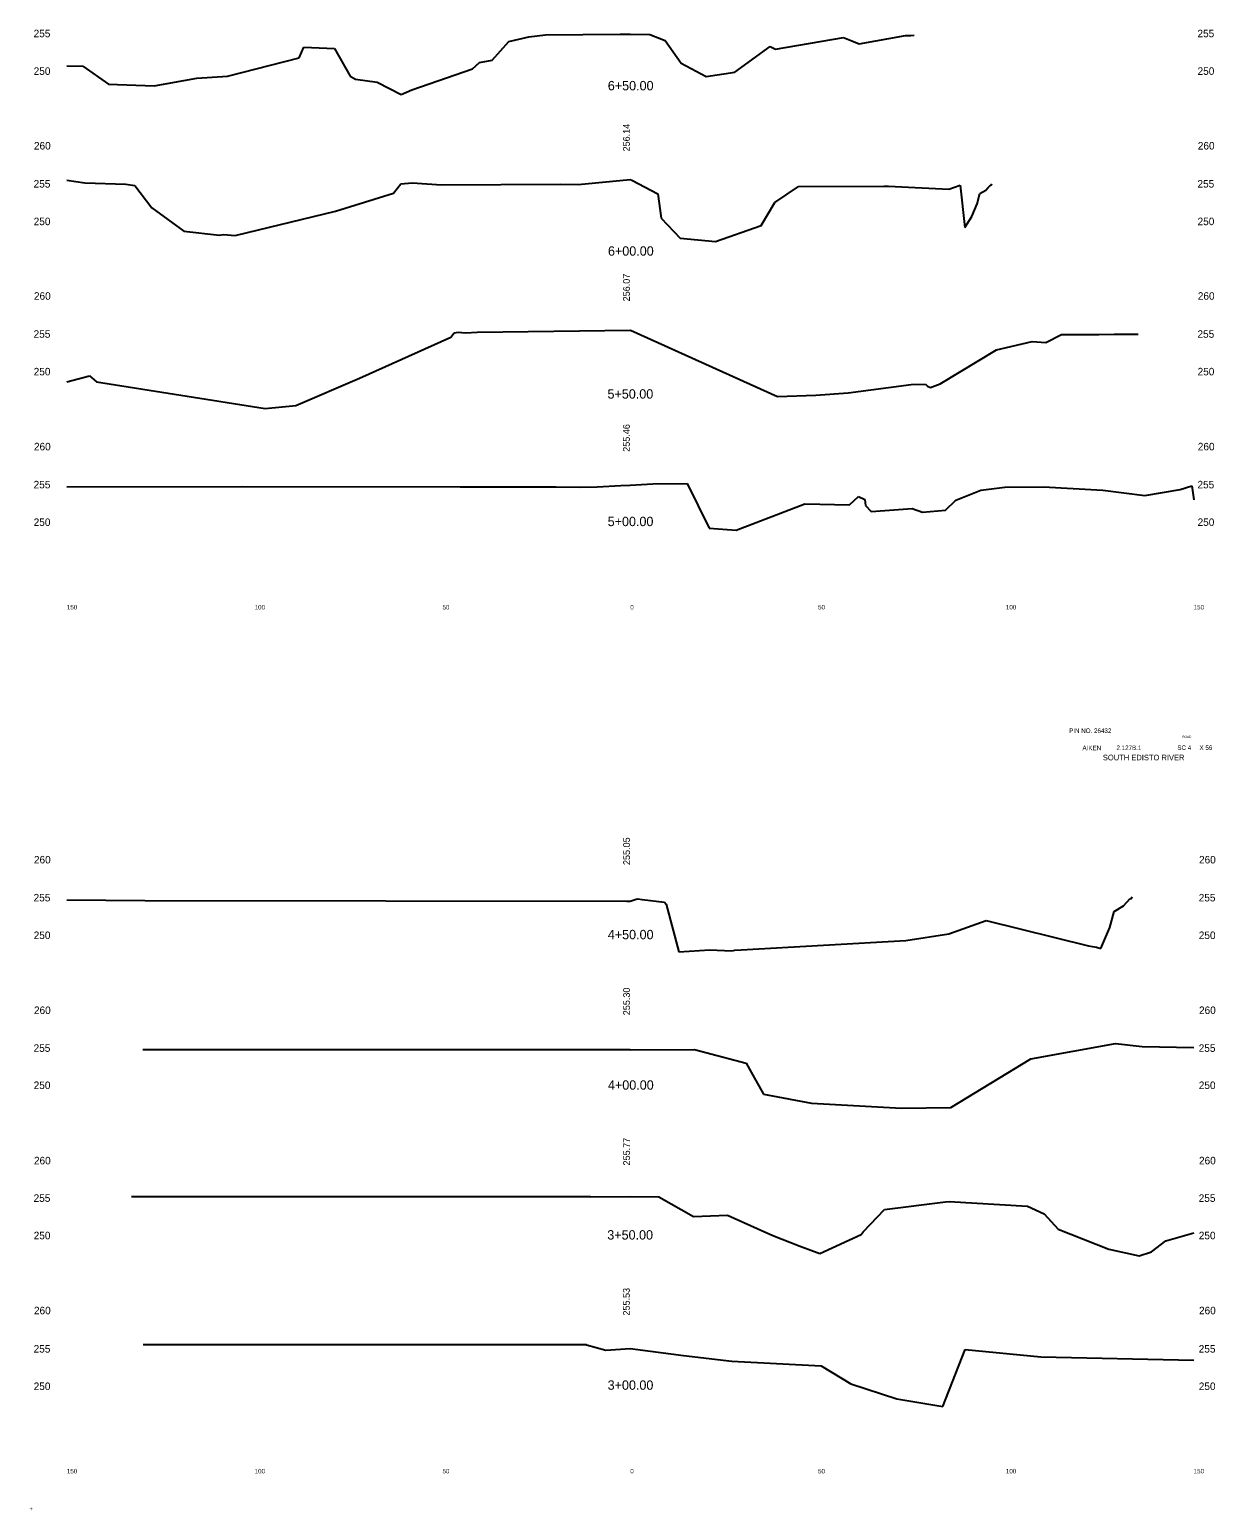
# Model space of a CAD drawing. Extents: x 557 to 872, y 628 to 2216.
# Drawn here: x 556.6 to 872.3, y 628 to 1022.2 of the extents above; entities that cross this region are included whole.
import ezdxf

# ---------------------------------------------------------------- set-up
doc = ezdxf.new("R2010")
doc.units = 0
for name, color, linetype in [('Level 1', 7, 'Continuous'), ('Level 10', 7, 'Continuous'), ('Level 13', 7, 'Continuous'), ('Level 3', 7, 'Continuous'), ('Level 60', 7, 'Continuous')]:
    doc.layers.add(name, color=color, linetype=linetype)

msp = doc.modelspace()

# ---------------------------------------------------------------- linework, layer by layer
at = {"layer": 'Level 60'}
for p, q in [((628.42, 1014.65), (629.6, 1017.48)), ((629.6, 1017.48), (637.79, 1017.18)), ((637.79, 1017.18), (641.99, 1009.73)), ((679.77, 1014.03), (684.22, 1018.98)), ((684.22, 1018.98), (689.54, 1020.23)), ((689.54, 1020.23), (693.95, 1020.75)), ((693.95, 1020.75), (713.85, 1020.96)), ((713.85, 1020.96), (716.54, 1020.93)), ((716.54, 1020.93), (721.78, 1020.86)), ((721.78, 1020.86), (725.81, 1019.29)), ((725.81, 1019.29), (730.12, 1013.19)), ((744.34, 1010.87), (753.83, 1017.71)), ((753.83, 1017.71), (755.24, 1017)), ((755.24, 1017), (773.34, 1020.09)), ((773.34, 1020.09), (775.5, 1019.22)), ((775.5, 1019.22), (777.5, 1018.41)), ((777.5, 1018.41), (789.84, 1020.58)), ((789.84, 1020.58), (791.27, 1020.64)), ((791.27, 1020.64), (792.16, 1020.65)), ((609.31, 1009.8), (628.42, 1014.65)), ((674.52, 1011.7), (676.36, 1013.43)), ((676.36, 1013.43), (679.77, 1014.03)), ((730.12, 1013.19), (736.79, 1009.69)), ((566.54, 1012.48), (570.83, 1012.4)), ((570.83, 1012.4), (577.58, 1007.64)), ((589.75, 1007.24), (601.14, 1009.26)), ((601.14, 1009.26), (609.31, 1009.8)), ((641.99, 1009.73), (643.38, 1009.01)), ((658.39, 1006.17), (674.52, 1011.7)), ((736.79, 1009.69), (744.34, 1010.87)), ((577.58, 1007.64), (589.75, 1007.24)), ((643.38, 1009.01), (649.14, 1008.15)), ((649.14, 1008.15), (655.55, 1004.86)), ((655.55, 1004.86), (658.39, 1006.17)), ((566.54, 982.08), (571.3, 981.41)), ((702.69, 980.97), (716.54, 982.28)), ((716.54, 982.28), (716.93, 982.08)), ((716.93, 982.08), (723.85, 978.48)), ((571.3, 981.41), (582.25, 981.01)), ((582.25, 981.01), (584.65, 980.65)), ((584.65, 980.65), (589.16, 974.72)), ((638.07, 973.87), (653.47, 978.6)), ((653.47, 978.6), (655.48, 981.08)), ((655.48, 981.08), (658.48, 981.41)), ((658.48, 981.41), (666.26, 980.84)), ((666.26, 980.84), (697.95, 981)), ((697.95, 981), (702.69, 980.97)), ((723.85, 978.48), (724.74, 971.93)), ((755, 976.1), (761.33, 980.42)), ((761.33, 980.42), (784.06, 980.46)), ((784.06, 980.46), (785.28, 980.48)), ((785.28, 980.48), (801.35, 979.69)), ((801.35, 979.69), (804.38, 980.77)), ((804.38, 980.77), (805.59, 969.44)), ((808.9, 975.74), (809.62, 978.51)), ((809.62, 978.51), (811.23, 979.45)), ((811.23, 979.45), (811.86, 980.12)), ((811.86, 980.12), (812.44, 980.78)), ((812.44, 980.78), (812.66, 980.64)), ((812.66, 980.64), (812.83, 981.08)), ((589.16, 974.72), (597.72, 968.47)), ((611.39, 967.37), (638.07, 973.87)), ((751.43, 970.05), (755, 976.1)), ((807.5, 972.45), (808.9, 975.74)), ((724.74, 971.93), (729.83, 966.61)), ((739.22, 965.74), (751.43, 970.05)), ((805.59, 969.44), (807.5, 972.45)), ((597.72, 968.47), (607.17, 967.41)), ((607.17, 967.41), (608.2, 967.62)), ((608.2, 967.62), (611.39, 967.37)), ((729.83, 966.61), (739.22, 965.74)), ((644.46, 929.39), (668.79, 940.25)), ((668.79, 940.25), (669.67, 941.44)), ((669.67, 941.44), (670.73, 941.6)), ((670.73, 941.6), (672.63, 941.46)), ((672.63, 941.46), (675.77, 941.61)), ((675.77, 941.61), (716.64, 942.14)), ((716.64, 942.14), (755.7, 924.48)), ((814.01, 936.9), (823.58, 939.13)), ((823.58, 939.13), (827.21, 938.91)), ((827.21, 938.91), (831.38, 941.01)), ((831.38, 941.01), (841.3, 941.03)), ((841.3, 941.03), (845.34, 941.09)), ((845.34, 941.09), (851.78, 941.05)), ((799.08, 927.89), (814.01, 936.9)), ((566.54, 928.42), (572.54, 929.99)), ((572.54, 929.99), (574.39, 928.41)), ((574.39, 928.41), (619.37, 921.34)), ((627.5, 922.14), (644.46, 929.39)), ((774.52, 925.47), (791.31, 927.68)), ((791.31, 927.68), (795.13, 927.77)), ((795.13, 927.77), (795.64, 927.24)), ((795.64, 927.24), (796.49, 926.85)), ((796.49, 926.85), (797.66, 927.29)), ((797.66, 927.29), (799.08, 927.89)), ((755.7, 924.48), (765.91, 924.82)), ((765.91, 924.82), (774.52, 925.47)), ((619.37, 921.34), (627.5, 922.14)), ((566.54, 900.41), (613.21, 900.52)), ((613.21, 900.52), (671.28, 900.41)), ((671.28, 900.41), (696.83, 900.45)), ((696.83, 900.45), (703.19, 900.37)), ((703.19, 900.37), (707.71, 900.48)), ((707.71, 900.48), (713.99, 900.8)), ((713.99, 900.8), (716.54, 900.93)), ((716.54, 900.93), (722.58, 901.23)), ((722.58, 901.23), (731.65, 901.34)), ((731.65, 901.34), (737.53, 889.48)), ((803.18, 896.93), (809.87, 899.54)), ((809.87, 899.54), (816.24, 900.38)), ((816.24, 900.38), (826.56, 900.43)), ((826.56, 900.43), (842.35, 899.53)), ((842.35, 899.53), (853.53, 898.16)), ((853.53, 898.16), (862.93, 899.7)), ((862.93, 899.7), (866.09, 900.69)), ((866.09, 900.69), (866.54, 896.94)), ((744.76, 888.9), (763, 895.94)), ((763, 895.94), (774.88, 895.61)), ((774.88, 895.61), (777.3, 897.86)), ((777.3, 897.86), (778.97, 897.08)), ((778.97, 897.08), (779.2, 895.45)), ((779.2, 895.45), (780.66, 893.89)), ((800.45, 894.2), (803.18, 896.93)), ((780.66, 893.89), (791.56, 894.67)), ((791.56, 894.67), (794.38, 893.72)), ((794.38, 893.72), (800.45, 894.2)), ((737.53, 889.48), (744.76, 888.9)), ((566.54, 790.48), (587.27, 790.32)), ((587.27, 790.32), (715.66, 790.1)), ((715.66, 790.1), (716.54, 790.1)), ((716.54, 790.1), (718.15, 790.63)), ((718.15, 790.63), (718.58, 790.75)), ((718.58, 790.75), (719.67, 790.62)), ((719.67, 790.62), (725.64, 789.87)), ((725.64, 789.87), (726.13, 789.35)), ((726.13, 789.35), (729.47, 776.69)), ((845.38, 787.41), (847.84, 788.88)), ((847.84, 788.88), (848.78, 789.88)), ((848.78, 789.88), (849.61, 790.84)), ((849.61, 790.84), (849.94, 790.64)), ((849.94, 790.64), (850.17, 791.28)), ((801.39, 781.48), (811.33, 785.03)), ((811.33, 785.03), (838.57, 778.27)), ((844.24, 783.13), (845.38, 787.41)), ((789.88, 779.71), (801.39, 781.48)), ((841.8, 777.56), (844.24, 783.13)), ((729.47, 776.69), (737.74, 777.18)), ((737.74, 777.18), (743.59, 776.93)), ((743.59, 776.93), (744.35, 777.12)), ((744.35, 777.12), (746.03, 777.15)), ((746.03, 777.15), (789.88, 779.71)), ((838.57, 778.27), (840.69, 777.93)), ((840.69, 777.93), (841.8, 777.56)), ((716.53, 750.6), (586.8, 750.6)), ((716.53, 750.6), (733.62, 750.68)), ((733.62, 750.68), (747.41, 747.02)), ((823.15, 748.17), (845.71, 752.23)), ((845.71, 752.23), (852.86, 751.46)), ((852.86, 751.46), (866.54, 751.16)), ((747.41, 747.02), (749.14, 743.84)), ((801.92, 735.19), (823.15, 748.17)), ((749.14, 743.84), (752.01, 738.75)), ((752.01, 738.75), (752.97, 738.58)), ((752.97, 738.58), (764.82, 736.38)), ((764.82, 736.38), (788.71, 735.07)), ((788.71, 735.07), (801.92, 735.19)), ((705.94, 711.39), (583.76, 711.39)), ((705.94, 711.39), (716.54, 711.54)), ((716.54, 711.54), (724.18, 711.46)), ((724.18, 711.46), (733.34, 706.2)), ((784.24, 708.07), (800.43, 710.14)), ((800.43, 710.14), (801.44, 710.21)), ((801.44, 710.21), (822.34, 708.96)), ((733.34, 706.2), (742.46, 706.51)), ((742.46, 706.51), (750.33, 703)), ((778.55, 702.07), (784.24, 708.07)), ((822.34, 708.96), (826.7, 706.89)), ((826.7, 706.89), (830.48, 702.79)), ((750.33, 703), (754.5, 701.15)), ((777.97, 701.42), (778.55, 702.07)), ((830.48, 702.79), (843.97, 697.53)), ((859.11, 699.69), (866.54, 701.88)), ((754.5, 701.15), (761.55, 698.42)), ((761.55, 698.42), (767.04, 696.31)), ((767.04, 696.31), (777.97, 701.42)), ((855.35, 696.82), (859.11, 699.69)), ((843.97, 697.53), (852.06, 695.72)), ((852.06, 695.72), (855.35, 696.82)), ((704.91, 672.07), (586.82, 672.07)), ((704.91, 672.07), (710.03, 670.64)), ((710.03, 670.64), (716.54, 671.06)), ((716.54, 671.06), (730.68, 669.22)), ((799.72, 655.64), (805.69, 670.8)), ((805.69, 670.8), (825.81, 668.8)), ((730.68, 669.22), (743.6, 667.71)), ((743.6, 667.71), (767.34, 666.4)), ((767.34, 666.4), (775.26, 661.68)), ((825.81, 668.8), (866.54, 667.91)), ((775.26, 661.68), (787.49, 657.66)), ((787.49, 657.66), (799.72, 655.64))]:
    msp.add_line(p, q, dxfattribs=at)

# ---------------------------------------------------------------- texts
at = {"layer": 'Level 1'}
for s, height, p in [('6+50.00', 2.5, (710.56, 1006)), ('6+00.00', 2.5, (710.6, 961.98)), ('5+50.00', 2.5, (710.48, 923.93)), ('5+00.00', 2.5, (710.52, 889.98)), ('PIN NO. 26432', 1.2, (833.38, 834.92)), ('ROAD', 0.6, (863.53, 833.59)), ('AIKEN', 1.2, (836.93, 830.33)), ('SOUTH EDISTO RIVER', 1.5, (842.36, 827.63)), (' 2.127B.1', 1.2, (845.53, 830.38)), ('SC 4', 1.2, (862.2, 830.4)), ('X 56', 1.2, (868.09, 830.41)), ('4+50.00', 2.5, (710.56, 780)), ('4+00.00', 2.5, (710.6, 739.95)), ('3+50.00', 2.5, (710.42, 700.05)), ('3+00.00', 2.5, (710.51, 660.06))]:
    msp.add_text(s, height=height, dxfattribs=at).set_placement(p)
at = {"layer": 'Level 10'}
for s, p in [('256.14', (716.42, 989.73)), ('256.07', (716.43, 949.82)), ('255.46', (716.42, 909.77)), ('255.05', (716.45, 799.76)), ('255.30', (716.45, 759.77)), ('255.77', (716.46, 719.78)), ('255.53', (716.41, 679.81))]:
    msp.add_text(s, height=1.8, rotation=90, dxfattribs=at).set_placement(p)
at = {"layer": 'Level 13'}
for s, p in [('150', (566.54, 867.8)), ('100', (616.54, 867.8)), ('50', (666.54, 867.8)), ('0', (716.54, 867.8)), ('50', (766.54, 867.8)), ('100', (816.54, 867.8)), ('150', (866.54, 867.8)), ('150', (566.54, 637.8)), ('100', (616.54, 637.8)), ('50', (666.54, 637.8)), ('0', (716.54, 637.8)), ('50', (766.54, 637.8)), ('100', (816.54, 637.8)), ('150', (866.54, 637.8)), ('+', (556.54, 627.8))]:
    msp.add_text(s, height=1.2, dxfattribs=at).set_placement(p)
at = {"layer": 'Level 3'}
for s, p in [(' 255', (556.94, 1020.13)), (' 255', (866.81, 1020.13)), (' 250', (556.96, 1010.12)), (' 250', (866.84, 1010.12)), (' 260', (557.03, 990.24)), (' 260', (866.9, 990.24)), (' 255', (556.94, 980.11)), (' 255', (866.81, 980.11)), (' 250', (556.96, 970.1)), (' 250', (866.84, 970.1)), (' 260', (557.03, 950.25)), (' 260', (866.9, 950.25)), (' 255', (556.94, 940.13)), (' 255', (866.81, 940.13)), (' 250', (556.96, 930.12)), (' 250', (866.84, 930.12)), (' 260', (557.03, 910.16)), (' 260', (866.9, 910.16)), (' 255', (556.94, 900.04)), (' 255', (866.81, 900.04)), (' 250', (556.96, 890.03)), (' 250', (866.84, 890.03)), (' 260', (557.03, 800.18)), (' 260', (867.22, 800.18)), (' 255', (556.94, 790.07)), (' 255', (867.14, 790.07)), (' 250', (556.96, 780.06)), (' 250', (867.16, 780.06)), (' 260', (557.03, 760.1)), (' 260', (867.22, 760.1)), (' 255', (556.94, 750.03)), (' 255', (867.14, 750.03)), (' 250', (556.96, 740.13)), (' 250', (867.16, 740.13)), (' 260', (557.03, 720.08)), (' 260', (867.22, 720.08)), (' 255', (556.94, 710.09)), (' 255', (867.14, 710.09)), (' 250', (556.96, 700.13)), (' 250', (867.16, 700.13)), (' 260', (557.03, 680.16)), (' 260', (867.22, 680.16)), (' 255', (556.94, 669.96)), (' 255', (867.14, 669.96)), (' 250', (556.96, 660)), (' 250', (867.16, 660))]:
    msp.add_text(s, height=2, dxfattribs=at).set_placement(p)

doc.saveas('drawing.dxf')
